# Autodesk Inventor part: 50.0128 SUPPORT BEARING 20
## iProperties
Created: 2007-07
Part Number: 50.0128 SUPPORT BEARING 20
Material: Steel
Document SubType Name: Modeling
Designer: Andy Moles
Density: 7.85 g/cm^3
Author: Andy Moles
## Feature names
1. Base1
